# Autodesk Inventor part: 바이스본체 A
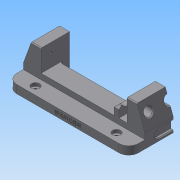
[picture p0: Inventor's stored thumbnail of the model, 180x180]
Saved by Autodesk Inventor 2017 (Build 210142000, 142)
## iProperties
Created: 2017-04
Part Number: 바이스본체 A
Material: 알루미늄 6061
Document SubType Name: Modeling
Designer: mduedu
Density: 2.71 g/cm^3
Mass: 324.154 g
Surface Area: 276.938 cm^2
Volume: 119.614 cm^3
Appearance: 기본값
Author: mduedu
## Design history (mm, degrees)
sketch "스케치1"
  geometry: L1 (-75, 0)-(75, 0); L2 (-75, 0)-(-75, 17); L3 (-53, 17)-(53, 17); L4 (75, 17)-(75, 0); L5 (-75, 17)-(-65.173, 44); L6 (-65.173, 44)-(-53, 44); L7 (-53, 44)-(-53, 17); L8 (0, 0)-(0, 17); L9 (75, 17)-(65.173, 44); L10 (65.173, 44)-(53, 44); L11 (53, 44)-(53, 17); 1 further point
  constraints: 22 end point, 4 perpendicular, 2 horizontal alignment, 2 midpoint, 2 symmetric about line, 1 coincident, 1 collinear, 1 horizontal, 1 vertical
  dimensions: "d0" = 150 distance of L1.start L1.end; "d1" = 17 distance of L1.start L2.end; "d2" = 27 distance of L3.start L6.end; "d3" = 22 distance of L3.start L2.end; "d4" = 70 deg angle of L3 L5; "d54" = 20 deg angle of L9 L4
extrude "돌출1" new body sketch "스케치1" stored distance "d5" = 70; taper "d6" = 0 deg
sketch "스케치2"
  geometry: L1 (0, 70)-(106, 70) reference; L2 (106, 70)-(106, 0) reference; L3 (106, 0)-(0, 0) reference; L4 (0, 47)-(106, 47); L5 (106, 47)-(106, 23); L6 (106, 23)-(0, 23); L7 (0, 23)-(0, 47); L8 (0, 70)-(0, 0) reference; 2 further points
  constraints: 8 end point, 2 parallel, 2 point on line, 1 horizontal, 1 horizontal alignment, 1 midpoint, 1 perpendicular
  dimensions: "d7" = 24 distance between parallel lines of L6 L4
extrude "돌출2" cut sketch "스케치2" stored distance "d9" = 70; taper "d10" = 0 deg
sketch "스케치3"
  geometry: L1 (22, -23)-(128, -23) reference; L2 (128, -47)-(22, -47) reference; L3 (22, -18)-(128, -18); L4 (128, -52)-(22, -52); L5 (22, -18)-(22, -52); L6 (128, -18)-(128, -52); 1 further point
  constraints: 8 end point, 3 parallel, 2 point on line, 1 perpendicular
  dimensions: "d11" = 5 distance between parallel lines of L3 L1; "d12" = 5 distance between parallel lines of L4 L2
extrude "돌출3" cut sketch "스케치3" distance "d13" = 12; taper "d14" = 0 deg
fillet "모깎기1" dims "d15" = 3, "d16" = 3
sketch "스케치4"
  geometry: L1 (103, 23)-(3, 23) reference; L2 (0, 26)-(0, 0) reference; L3 (106, 0)-(0, 0) reference; L4 (106, 26)-(106, 0) reference; L5 (96, 0)-(90, 0); L6 (90, 0)-(90, 19.5); L7 (96, 19.5)-(96, 0); L8 (90, 19.5)-(96, 19.5); A1 r 3 centre (3, 26) between (0, 26) and (3, 23) reference; A2 r 3 centre (103, 26) between (103, 23) and (106, 26) reference; 1 further point
  constraints: 8 end point, 2 perpendicular, 1 horizontal, 1 parallel, 1 point on line
  dimensions: "d17" = 10 distance between parallel lines of L7 L4; "d18" = 6 distance between parallel lines of L7 L6; "d27" = 3.5 distance between parallel lines of L8 L1
extrude "돌출4" join sketch "스케치4" distance "d19" = 12; taper "d20" = 0 deg
chamfer "모따기1" distance "d21" = 3; stored, may be unused: second distance "d22" = 2, angle "d23" = 45 deg
chamfer "모따기2" distance "d24" = 3; stored, may be unused: second distance "d25" = 2, angle "d26" = 45 deg
sketch "스케치5"
  geometry: L1 (-15.5, 35.8)-(-15.5, -25.8) reference; L2 (19.5, 0)-(0, 0) reference; C1 r 6.5 at (9.5, 15); 1 further point
  constraints: 1 centre point
  dimensions: "d28" = 13 diameter of C1; "d30" = 15 distance from line of C1.centre L2; "d31" = 25 distance from line of C1.centre L1
extrude "돌출5" cut sketch "스케치5" stored distance "d32" = 12; taper "d33" = 0 deg
sketch "스케치6"
  geometry: C1 r 5 at (-10, 15); C2 r 5 at (-60, 15); A1 r 6.5 centre (-10, 15) between (-15.766, 12) and (-4.234, 12) reference; A2 r 6.5 centre (-60, 15) between (-65.766, 12) and (-54.234, 12) reference; 1 further point
  constraints: 2 centre point, 2 coincident
  dimensions: "d34" = 10 diameter of C1; "d35" = 10 diameter of C2 (= d34)
extrude "돌출6" cut sketch "스케치6" stored distance "d36" = 12; taper "d37" = 0 deg
chamfer "모따기3" distance "d38" = 1; stored, may be unused: second distance "d39" = 2, angle "d40" = 45 deg
chamfer "모따기4" distance "d41" = 1; stored, may be unused: second distance "d42" = 2, angle "d43" = 45 deg
sketch "스케치7"
  geometry: L1 (-35, 35.8)-(-35, -25.8) reference; L2 (-70, 0)-(0, 0) reference; C1 r 5 at (-35, 15); 1 further point
  constraints: 1 centre point, 1 point on line
  dimensions: "d44" = 10 diameter of C1; "d45" = 15 distance from line of C1.centre L2
extrude "돌출7" cut sketch "스케치7" stored distance "d46" = 12; taper "d47" = 0 deg
chamfer "모따기5" distance "d48" = 1; stored, may be unused: second distance "d49" = 2, angle "d50" = 45 deg
node "작업축1"
sketch "스케치8"
  geometry: L1 (-105, 32)-(105, 32) reference; L2 (58, 32)-(64, 32); L3 (64, 32)-(64, 40); L4 (64, 40)-(58, 40); L5 (58, 40)-(58, 32); L6 (53, 38)-(53, 26) reference; 1 further point
  constraints: 8 end point, 2 parallel, 1 horizontal, 1 perpendicular, 1 point on line
  dimensions: "d51" = 5 distance from line of L6 L2.start; "d52" = 6 distance of L3.end L4.end; "d53" = 16 diameter of L4 L1
revolve "회전1" sketch "스케치8" stored, may be unused: angle "d55" = 90 deg
fillet "모깎기2"
chamfer "모따기6" distance "d56" = 1; stored, may be unused: second distance "d57" = 2, angle "d58" = 45 deg
sketch "스케치9"
  geometry: L1 (17.5, 3)-(52.5, 3); L2 (52.5, 13)-(17.5, 13); L3 (70, 0)-(0, 0) reference; L4 (17.5, 8)-(52.5, 8); A1 r 5 centre (17.5, 8) between (17.5, 13) and (17.5, 3); A2 r 5 centre (52.5, 8) between (52.5, 3) and (52.5, 13); 3 further points
  constraints: 6 end point, 4 point on circle, 3 tangent, 2 centre point, 2 midpoint, 2 parallel, 1 horizontal, 1 vertical alignment
  dimensions: "d59" = 35 distance of L4.start L4.end; "d61" = 5 radius of A2; "d62" = 8 distance between parallel lines of L3 L4
extrude "돌출8" cut sketch "스케치9" distance "d63" = 3; taper "d64" = 0 deg
chamfer "모따기7" distance "d65" = 1; stored, may be unused: second distance "d66" = 2, angle "d67" = 45 deg
chamfer "모따기8" distance "d68" = 1; stored, may be unused: second distance "d69" = 2, angle "d70" = 45 deg
feature "분할1"
sketch "스케치10"
  geometry: L1 (35, 27)-(0, 27) reference; L2 (0, 0)-(0, 27) reference; 1 further point
  dimensions: "d85" = 11.5 distance from line of point (12, 15.5) L1; "d86" = 12 distance from line of point (12, 15.5) L2
hole "구멍1" sketch "스케치10" at (12, 15.5) diameter "d71" = 3.242; stored, may be unused: countersink angle "d75" = 90 deg, drill point angle "d77" = 120 deg; dims "d72" = 8, "d73" = 4, "d74" = 2, "d76" = 10
sketch "스케치11"
  geometry: A1 r 5 centre (17.5, 8) between (17.5, 13) and (17.5, 3) reference; 1 further point
  constraints: 1 coincident
hole "구멍3" sketch "스케치11" at (17.5, 8) diameter "d78" = 2.459; stored, may be unused: countersink angle "d82" = 90 deg, drill point angle "d84" = 120 deg; dims "d79" = 4.5, "d80" = 4, "d81" = 2, "d83" = 6
sketch "스케치13"
  geometry: L1 (75, 0)-(75, 35) reference; L2 (-75, 0)-(-75, 35) reference; L3 (-75, 35)-(75, 35); L4 (75, 35)-(75, 55); L5 (75, 55)-(-75, 55); L6 (-75, 55)-(-75, 35); 1 further point
  constraints: 8 end point, 2 parallel, 1 horizontal, 1 perpendicular, 1 point on line
  dimensions: "d90" = 20 distance between parallel lines of L5 L3; "d94" = 150 distance of L4.end L5.end (derived)
extrude "돌출9" join sketch "스케치13" distance "d92" = 10; taper "d93" = 0 deg
sketch "스케치14"
  geometry: L1 (-75, -35)-(-75, -55) reference; L2 (75, -55)-(75, -35) reference; L3 (-75, -45)-(75, -45); 3 further points
  constraints: 2 end point, 2 midpoint, 2 point on line
  dimensions: "d95" = 50 horizontal distance of point (-50, -45) point (0, 0); "d96" = 100 distance of point (50, -45) point (-50, -45)
fillet "모깎기3" dims "d97" = 12
chamfer "모따기9" distance "d98" = 1; stored, may be unused: second distance "d99" = 2, angle "d100" = 45 deg
hole "구멍4" sketch "스케치14" diameter "d101" = 4.134; stored, may be unused: countersink angle "d105" = 90 deg, drill point angle "d107" = 118 deg; dims "d102" = 6, "d103" = 10, "d104" = 4, "d106" = 8
sketch "스케치15"
  geometry: L1 (0, 0)-(126, 0) reference; 3 further points
  constraints: 1 midpoint, 1 vertical alignment, 1 other
  dimensions: "d109" = 5 distance from line of point (63, 5) L1
feature "엠보싱2" sketch "스케치15" dims "d0" = 150, "d1" = 17, "d2" = 27, "d3" = 22, "d4" = 70 deg, "d54" = 20 deg, "d110" = 0.5, "d111" = 0
node "솔리드1"
mirror "대칭1"
mirror "대칭2"
mirror "대칭3"
mirror "대칭4"
node "투영된 루프1"
